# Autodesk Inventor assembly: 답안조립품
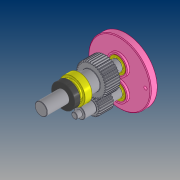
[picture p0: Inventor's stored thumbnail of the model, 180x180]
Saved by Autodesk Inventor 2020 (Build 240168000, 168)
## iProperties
Created: 2020-07
Part Number: 답안조립품
Document SubType Name: Assembly
Designer: PC312-
Author: PC312-
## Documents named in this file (9)
- C:\Users\PC312-\Desktop\700718V1013\답안조립품.iam
- C:\Users\PC312-\Desktop\700718V1013\본체.ipt
- C:\Users\PC312-\Desktop\700718V1013\오일 실 17 32 8.ipt
- C:\Users\PC312-\Desktop\700718V1013\커버.ipt
- C:\Users\PC312-\Desktop\700718V1013\오일 실 8 22 7.ipt
- C:\Users\PC312-\Desktop\700718V1013\서브 축.ipt
- C:\Users\PC312-\Desktop\700718V1013\베어링 608.ipt
- C:\Users\PC312-\Desktop\700718V1013\베어링 6003.ipt
- C:\Users\PC312-\Desktop\700718V1013\메인 축.ipt
